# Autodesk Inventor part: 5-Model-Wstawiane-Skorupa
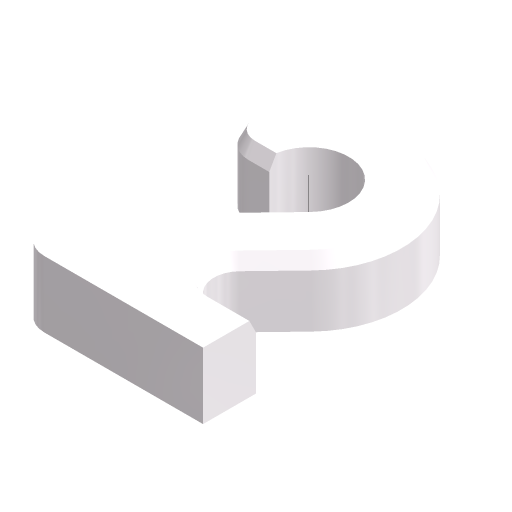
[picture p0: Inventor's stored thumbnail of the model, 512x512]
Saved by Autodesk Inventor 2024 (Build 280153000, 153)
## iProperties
Company: ATC
Shininess: 21.0
Length Units: 11269
Angle Units: 11279
Time Units: 11290
Mass Units: 11283
Length Display Precision: 3
Angle Display Precision: 2
Compacted: True
Created: 2023-03
Part Number: 5-Model-Wstawiane-Skorupa
Document SubType Name: Modeling
Designer: Andrzej Jaskulski
Material: Kurs-AJ
Density: 1 g/cm^3
Appearance: Kurs-AJ
Checked By: A.J.
Engr Approved By: Andrzej Jaskulski
Mfg Approved By: Andrzej Jaskulski
Authority: A.J.
Density: 0.0
Volumn: 0.0
Area: 0.0
PropertySet Name: Model Information
Control State: 0
Master: False
Checked Out: False
Title: A.J.: Kurs R2024-MEP
Author: Andrzej Jaskulski
Revision Number: 1/24
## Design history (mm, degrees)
sketch "Zarys dwójki"
  geometry: L1 (140, 0.063)-(0, 0.063) reference; L2 (0, 0.063)-(0, 34.389) reference; L3 (0, 150.063)-(40, 150.063); L4 (140, 0.063)-(140, 40.063); L5 (140, 40.063)-(61.086, 40.063); L6 (61.086, 40.063)-(120.354, 101.437); L7 (91.58, 129.223)-(0, 34.389); A1 r 30 centre (70, 150.063) between (91.58, 129.223) and (40, 150.063); A2 r 70 centre (70, 150.063) between (120.354, 101.437) and (0, 150.063)
  constraints: 14 end point, 4 perpendicular, 4 point on circle, 2 centre point, 2 parallel, 2 tangent, 1 coincident
  dimensions: "d0" = 140 distance of L1.start L1.end; "d1" = 150 vertical distance of A1.centre L1.end; "d2" = 70 horizontal distance of L1.end A1.centre; "d3" = 46 deg angle of L6 L5; "d4" = 150 distance of L3.start L1.end (= d1); "d5" = 30 radius of A1; "d6" = 70 radius of A2
extrude "Dwójka" new body sketch "Zarys dwójki" distance "d7" = 50; taper "d8" = 0 deg
node "Oś walca"
fillet "Zaokrąglenie 3 x R30" dims "d12" = 20
chamfer "Faza 5 x 10" distance "d13" = 5; stored, may be unused: second distance "d14" = 10, angle "d15" = 45 deg
node "Bryła1"
node "Korpusy bryłowe"
node "Korpusy powierzchniowe"
other parameters: "d9" = 90 deg
